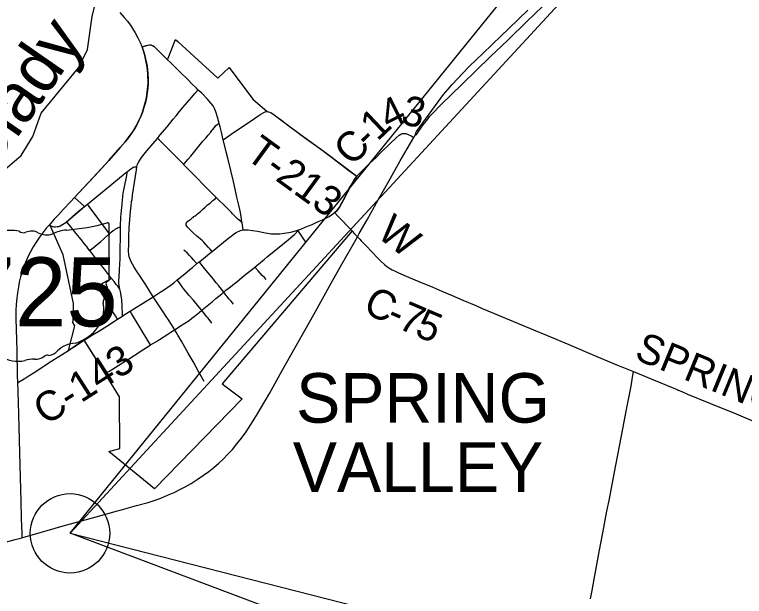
# Model space of a CAD drawing. Extents: x -19.5 to 44.1, y 0 to 22.
# Drawn here: x 5.174 to 6.569, y 16.047 to 17.159 of the extents above; entities that cross this region are included whole.
import ezdxf

# ---------------------------------------------------------------- set-up
doc = ezdxf.new("R2010")
doc.units = 0
for name, color, linetype in [('GM_X_City_Street', 7, 'Continuous'), ('GM_X_Corporation', 7, 'Continuous'), ('GM_X_Corporation_Text', 7, 'Continuous'), ('GM_X_County_Road', 7, 'Continuous'), ('GM_X_County_Road_Text', 7, 'Continuous'), ('GM_X_Minor_River', 7, 'Continuous'), ('GM_X_Minor_River_Text', 7, 'Continuous'), ('GM_X_State_Location', 7, 'Continuous'), ('GM_X_State_Route', 7, 'Continuous'), ('GM_X_State_Shield', 7, 'Continuous'), ('GM_X_Township_Road', 7, 'Continuous'), ('GM_X_Township_Road_Text', 7, 'Continuous'), ('GM_X_Township_Subdivision', 7, 'Continuous'), ('GM_X_US_Route', 7, 'Continuous'), ('SH_Text', 7, 'Continuous')]:
    doc.layers.add(name, color=color, linetype=linetype)

msp = doc.modelspace()

# ---------------------------------------------------------------- linework, layer by layer
at = {"layer": 'GM_X_City_Street'}
for points in [[(5.4716, 17.0678), (5.4663, 17.0729)], [(5.525, 17.015), (5.5213, 17.0185), (5.5123, 17.0274), (5.5054, 17.0344), (5.49, 17.0498), (5.4716, 17.0678)], [(5.4468, 16.9226), (5.4517, 16.9285), (5.4654, 16.9449), (5.477, 16.959), (5.4825, 16.9656), (5.4891, 16.9738), (5.4951, 16.981), (5.5038, 16.9912), (5.5124, 17.0012), (5.5185, 17.0081), (5.5238, 17.0138), (5.525, 17.015)], [(5.5651, 16.9511), (5.5619, 16.9628), (5.5585, 16.9734), (5.556, 16.9797), (5.5534, 16.9845), (5.5498, 16.9894), (5.5424, 16.9977), (5.5316, 17.0087), (5.525, 17.015)], [(5.5726, 16.92), (5.5742, 16.9211), (5.5877, 16.9304), (5.602, 16.9403), (5.6258, 16.9561), (5.6391, 16.9652), (5.6446, 16.9689), (5.6491, 16.9715), (5.6531, 16.9732), (5.6568, 16.974)], [(5.497, 16.8724), (5.4987, 16.8745), (5.5056, 16.8828), (5.5107, 16.8887), (5.5288, 16.9108), (5.534, 16.917), (5.5392, 16.9232), (5.5436, 16.9284), (5.5487, 16.9345), (5.5509, 16.9374), (5.552, 16.9388), (5.5557, 16.9433), (5.5581, 16.9463), (5.5617, 16.9496), (5.5651, 16.9511)], [(5.5726, 16.92), (5.5694, 16.9347), (5.5668, 16.9449), (5.5651, 16.9511)], [(5.4077, 16.8681), (5.4091, 16.8733), (5.4112, 16.8776), (5.4166, 16.886), (5.4268, 16.8985), (5.4468, 16.9226)], [(5.497, 16.8724), (5.4965, 16.873), (5.4923, 16.8776), (5.4887, 16.8814), (5.4827, 16.8874), (5.4639, 16.9063), (5.4572, 16.9128), (5.45, 16.9196), (5.4468, 16.9226)], [(5.6088, 16.7612), (5.6085, 16.7632), (5.607, 16.7724), (5.6055, 16.7808), (5.6043, 16.7867), (5.6025, 16.7949), (5.5999, 16.8053), (5.5988, 16.8101), (5.5973, 16.8167), (5.5923, 16.8398), (5.5872, 16.8612), (5.5813, 16.8845), (5.5781, 16.8966), (5.573, 16.9177), (5.5726, 16.92)], [(5.4386, 16.6199), (5.4245, 16.6423), (5.4194, 16.6502), (5.4124, 16.6609), (5.4081, 16.6677), (5.4026, 16.6766), (5.3995, 16.6823), (5.397, 16.6866), (5.3941, 16.6929), (5.3929, 16.6964), (5.3922, 16.7007), (5.3919, 16.7069), (5.3922, 16.7212), (5.3924, 16.7349), (5.3929, 16.7518), (5.3939, 16.7672), (5.3954, 16.7833), (5.3964, 16.7931), (5.3976, 16.8016), (5.3983, 16.8057), (5.3995, 16.8141), (5.4033, 16.838), (5.407, 16.8624), (5.4077, 16.8681)], [(5.3997, 16.8666), (5.4008, 16.8672), (5.4019, 16.8676), (5.4031, 16.868), (5.4039, 16.8681), (5.4053, 16.8682), (5.4077, 16.8681)], [(5.5595, 16.8093), (5.5594, 16.8094), (5.5485, 16.8203), (5.5377, 16.8313), (5.5338, 16.8353), (5.5241, 16.8449), (5.5089, 16.8602), (5.5079, 16.861), (5.4985, 16.8707), (5.497, 16.8724)], [(5.3131, 16.797), (5.345, 16.8231), (5.3744, 16.8469), (5.3887, 16.8588), (5.3896, 16.8594)], [(5.3761, 16.7537), (5.3761, 16.755), (5.377, 16.7718), (5.3774, 16.778), (5.378, 16.7848), (5.3787, 16.7904), (5.3795, 16.7977), (5.3802, 16.8039), (5.3809, 16.8113), (5.3816, 16.818), (5.3832, 16.827), (5.3881, 16.8513), (5.3883, 16.8526), (5.3896, 16.8594)], [(5.3896, 16.8594), (5.3961, 16.8643), (5.3997, 16.8666)], [(5.5513, 16.7064), (5.5502, 16.7077), (5.5479, 16.7106), (5.544, 16.7148), (5.5354, 16.7239), (5.5329, 16.7264), (5.5283, 16.7307), (5.5221, 16.7359), (5.5153, 16.7423), (5.508, 16.7491), (5.5048, 16.752), (5.5029, 16.7545), (5.5018, 16.7567), (5.5017, 16.7585), (5.5021, 16.7603), (5.5031, 16.7618), (5.5053, 16.764), (5.5106, 16.7683), (5.5135, 16.7705), (5.515, 16.7716), (5.5167, 16.7729), (5.519, 16.7745), (5.5207, 16.7757), (5.523, 16.7775), (5.5259, 16.7801), (5.529, 16.783), (5.5329, 16.7867), (5.5379, 16.7912), (5.5428, 16.7953), (5.5474, 16.799), (5.5529, 16.8037), (5.5579, 16.8079), (5.5595, 16.8093)], [(5.6088, 16.7612), (5.6061, 16.7636), (5.6009, 16.7681), (5.5957, 16.7731), (5.5922, 16.7766), (5.5905, 16.7784), (5.5887, 16.7806), (5.5857, 16.7837), (5.5828, 16.7868), (5.5787, 16.7905), (5.5595, 16.8093)], [(5.2734, 16.7633), (5.2746, 16.7642), (5.2773, 16.7667), (5.28, 16.7691), (5.2827, 16.7716), (5.2851, 16.7736), (5.2893, 16.7772), (5.2953, 16.7825), (5.3075, 16.7924), (5.3131, 16.797)], [(5.3554, 16.7403), (5.3535, 16.7428), (5.3164, 16.7926), (5.3131, 16.797)], [(5.715, 16.7473), (5.7208, 16.7493), (5.7294, 16.7529), (5.7355, 16.7554), (5.7424, 16.7582), (5.7489, 16.7609), (5.7564, 16.7642), (5.7625, 16.7671), (5.7688, 16.77), (5.7749, 16.7733), (5.7797, 16.7764), (5.7843, 16.7797), (5.7856, 16.7807)], [(5.2398, 16.7568), (5.2436, 16.7552), (5.2462, 16.7542), (5.2488, 16.7537), (5.2519, 16.7535), (5.2555, 16.7538), (5.2583, 16.7543), (5.2613, 16.7553), (5.2655, 16.7577), (5.2702, 16.7608), (5.2734, 16.7633)], [(5.3174, 16.7081), (5.3173, 16.7082), (5.3139, 16.7126), (5.3117, 16.7156), (5.3106, 16.7171), (5.3069, 16.7219), (5.3036, 16.7262), (5.2982, 16.7328), (5.2915, 16.741), (5.2813, 16.7535), (5.2755, 16.7607), (5.2734, 16.7633)], [(5.6107, 16.7477), (5.6088, 16.7612)], [(5.3554, 16.7403), (5.3586, 16.7431), (5.3624, 16.7462), (5.3648, 16.748), (5.3664, 16.749), (5.3701, 16.7512), (5.3719, 16.752), (5.3746, 16.7531), (5.3761, 16.7537)], [(5.3753, 16.6345), (5.3739, 16.6404), (5.3732, 16.6465), (5.3732, 16.6515), (5.3735, 16.6557), (5.3746, 16.6716), (5.3756, 16.6921), (5.3759, 16.7142), (5.3761, 16.7303), (5.3761, 16.7433), (5.3761, 16.7537)], [(5.5513, 16.7064), (5.5801, 16.7299), (5.5902, 16.7376), (5.5944, 16.7406), (5.5975, 16.7424), (5.6002, 16.7439), (5.6033, 16.7452), (5.606, 16.7463), (5.6107, 16.7477)], [(5.6107, 16.7477), (5.6157, 16.748), (5.6204, 16.7478), (5.6287, 16.7467), (5.6383, 16.745), (5.6535, 16.7421), (5.6645, 16.7401), (5.6691, 16.7399), (5.6729, 16.7398), (5.6769, 16.74), (5.6807, 16.7402), (5.6889, 16.7413), (5.6979, 16.7427), (5.7047, 16.7442), (5.7111, 16.746), (5.715, 16.7473)], [(5.6331, 16.6763), (5.6515, 16.6917), (5.6575, 16.6967), (5.6662, 16.7036), (5.6738, 16.7099), (5.6796, 16.7145), (5.6971, 16.7288), (5.7064, 16.7366), (5.709, 16.7389), (5.7116, 16.7414), (5.7127, 16.7427), (5.7133, 16.7437), (5.715, 16.7473)], [(5.7308, 16.7241), (5.7257, 16.732), (5.7229, 16.7359), (5.7206, 16.7392), (5.7174, 16.7438), (5.715, 16.7473)], [(5.3174, 16.7081), (5.3189, 16.7093), (5.324, 16.7136), (5.3388, 16.7256), (5.3442, 16.7305), (5.3535, 16.7388), (5.3554, 16.7403)], [(5.3592, 16.655), (5.3535, 16.6626), (5.3454, 16.6727), (5.3373, 16.6829), (5.3291, 16.6931), (5.3238, 16.7), (5.3174, 16.7081)], [(5.5225, 16.6831), (5.5212, 16.6846), (5.5157, 16.6905), (5.5118, 16.6946), (5.5082, 16.6988), (5.5035, 16.7036), (5.4975, 16.709)], [(5.5267, 16.6866), (5.5277, 16.6873), (5.5387, 16.6962), (5.5463, 16.7024), (5.5513, 16.7064)], [(5.4847, 16.652), (5.4869, 16.6538), (5.4996, 16.6639), (5.509, 16.6717), (5.5117, 16.674), (5.5139, 16.6759), (5.5212, 16.682), (5.5225, 16.6831)], [(5.5225, 16.6831), (5.5233, 16.6837), (5.5243, 16.6845), (5.5251, 16.6853), (5.5267, 16.6866)], [(5.5736, 16.6287), (5.5641, 16.6408), (5.5593, 16.6466), (5.5539, 16.6532), (5.5441, 16.6653), (5.5371, 16.674), (5.5278, 16.6852), (5.5267, 16.6866)], [(5.5736, 16.6287), (5.5742, 16.6292), (5.5779, 16.6321), (5.5867, 16.639), (5.5945, 16.6453), (5.5988, 16.6486), (5.6084, 16.6563), (5.6162, 16.6627), (5.6237, 16.669), (5.6293, 16.6732), (5.6331, 16.6763)], [(5.655, 16.6528), (5.6517, 16.6563), (5.6473, 16.6605), (5.6395, 16.6691), (5.6338, 16.6755), (5.6331, 16.6763)], [(5.3708, 16.577), (5.3695, 16.5789), (5.3665, 16.5835), (5.3581, 16.5965), (5.3542, 16.603), (5.3487, 16.6123), (5.3455, 16.6177), (5.3435, 16.6208), (5.3422, 16.6229), (5.3397, 16.627), (5.3376, 16.6309), (5.3365, 16.633), (5.3358, 16.6348), (5.3356, 16.636), (5.3354, 16.6378), (5.3357, 16.6393), (5.336, 16.6402), (5.3364, 16.6409), (5.3375, 16.6422), (5.3396, 16.644), (5.3422, 16.6457), (5.3443, 16.6469), (5.3503, 16.6501), (5.3522, 16.6511), (5.3574, 16.654), (5.3592, 16.655)], [(5.3753, 16.6345), (5.3709, 16.6399), (5.3682, 16.6433), (5.364, 16.6487), (5.3592, 16.655)], [(5.4386, 16.6199), (5.448, 16.626), (5.4521, 16.6286), (5.4554, 16.6307), (5.4601, 16.6338), (5.4647, 16.6367), (5.4666, 16.638), (5.4695, 16.6401), (5.4724, 16.6422), (5.4788, 16.6471), (5.4847, 16.652)], [(5.5316, 16.594), (5.5302, 16.5957), (5.5203, 16.6074), (5.5152, 16.6136), (5.5072, 16.6231), (5.4963, 16.6365), (5.4944, 16.639), (5.4889, 16.6464), (5.4847, 16.652)], [(5.3801, 16.5829), (5.38, 16.5865), (5.3792, 16.6018), (5.3788, 16.6141), (5.3778, 16.6221), (5.3765, 16.6295), (5.3753, 16.6345)], [(5.3948, 16.5923), (5.4018, 16.5968), (5.4386, 16.6199)], [(5.4798, 16.5566), (5.4781, 16.5595), (5.4726, 16.5684), (5.4691, 16.574), (5.4626, 16.5838), (5.4606, 16.5872), (5.4513, 16.6007), (5.4425, 16.614), (5.4386, 16.6199)], [(5.5316, 16.594), (5.5322, 16.5945), (5.5359, 16.5975), (5.5515, 16.6103), (5.5586, 16.6162), (5.5699, 16.6257), (5.5721, 16.6275), (5.5736, 16.6287)], [(5.5925, 16.6056), (5.5879, 16.6111), (5.5836, 16.6159), (5.5801, 16.6201), (5.5778, 16.6229), (5.5756, 16.6258), (5.5736, 16.6287)], [(5.3801, 16.5829), (5.3836, 16.5851), (5.3935, 16.5914), (5.3948, 16.5923)], [(5.4338, 16.5276), (5.4306, 16.5331), (5.3975, 16.5877), (5.3948, 16.5923)], [(5.4798, 16.5566), (5.4806, 16.5571), (5.4912, 16.5641), (5.4996, 16.5694), (5.5073, 16.5746), (5.5128, 16.5787), (5.5172, 16.5822), (5.5265, 16.5898), (5.5316, 16.594)], [(5.5511, 16.5696), (5.5438, 16.5787), (5.5415, 16.5814), (5.5363, 16.588), (5.5316, 16.594)], [(5.307, 16.5367), (5.3227, 16.5467), (5.3348, 16.5542), (5.3499, 16.5636), (5.3708, 16.577)], [(5.3708, 16.577), (5.3801, 16.5829)], [(5.4338, 16.5276), (5.438, 16.5302), (5.4449, 16.5345), (5.4509, 16.5383), (5.4666, 16.5483), (5.4727, 16.5522), (5.4798, 16.5566)], [(5.5362, 16.458), (5.5311, 16.4669), (5.5261, 16.4755), (5.5208, 16.4851), (5.5149, 16.4958), (5.5058, 16.5121), (5.493, 16.5347), (5.4859, 16.5464), (5.4824, 16.5521), (5.4798, 16.5566)], [(5.3821, 16.4948), (5.3917, 16.5005), (5.4023, 16.5073), (5.4211, 16.5195), (5.4312, 16.5259), (5.4338, 16.5276)], [(5.3473, 16.4763), (5.3489, 16.4761), (5.3505, 16.4759), (5.3516, 16.4761), (5.3539, 16.4769), (5.3589, 16.4798), (5.3661, 16.4846), (5.3731, 16.4893), (5.3799, 16.4934), (5.3821, 16.4948)]]:
    msp.add_lwpolyline(points, dxfattribs=at)
at = {"layer": 'GM_X_Corporation'}
msp.add_lwpolyline([(5.2669, 16.6997), (5.2417, 16.756), (5.2462, 16.7542), (5.2519, 16.7535), (5.2583, 16.7543), (5.2655, 16.7577), (5.2718, 16.762), (5.3075, 16.7924), (5.2885, 16.8096), (5.3316, 16.8559), (5.3539, 16.8802), (5.3758, 16.9048), (5.3851, 16.9157), (5.3991, 16.9346), (5.4097, 16.9525), (5.4152, 16.9644), (5.4183, 16.9726), (5.4212, 16.9815), (5.4237, 16.9906), (5.4259, 17.0003), (5.4292, 17.0275), (5.4288, 17.0457), (5.4273, 17.0596), (5.4244, 17.0747), (5.4222, 17.0837), (5.4176, 17.0974), (5.4286, 17.1007), (5.4326, 17.1012), (5.435, 17.1009), (5.4374, 17.1003), (5.4408, 17.0981), (5.4663, 17.0729), (5.4814, 17.1113), (5.4864, 17.1071), (5.5624, 17.0375), (5.5838, 17.0579), (5.6293, 16.9976), (5.6568, 16.974), (5.6593, 16.9735), (5.6634, 16.9718), (5.6699, 16.9677), (5.7056, 16.941), (5.7706, 16.8935), (5.8284, 16.8505), (5.8224, 16.8422), (5.817, 16.8333), (5.8024, 16.805), (5.7948, 16.7911), (5.7913, 16.786), (5.7892, 16.7836), (5.7856, 16.7807), (5.7931, 16.7727), (5.819, 16.7455), (5.5706, 16.4534), (5.6087, 16.4244), (5.4413, 16.2527), (5.3539, 16.3239), (5.3752, 16.3298), (5.3742, 16.4283), (5.3438, 16.4785), (5.307, 16.5367), (5.2766, 16.5171), (5.2891, 16.5642), (5.2844, 16.5716), (5.2858, 16.5727), (5.2862, 16.6067)], close=True, dxfattribs=at)
at = {"layer": 'GM_X_County_Road'}
for points in [[(5.4176, 17.0974), (5.4256, 17.0999), (5.4288, 17.1008), (5.4309, 17.1011), (5.4326, 17.1012), (5.4342, 17.1011), (5.4358, 17.1008), (5.4374, 17.1003), (5.4391, 17.0994), (5.4408, 17.0981), (5.4549, 17.084), (5.4663, 17.0729)], [(5.8284, 16.8505), (5.8377, 16.8601), (5.8527, 16.8749), (5.8642, 16.8854), (5.8735, 16.8946), (5.8917, 16.9125), (5.9034, 16.9237), (5.909, 16.9285), (5.912, 16.9305), (5.9136, 16.9312), (5.9152, 16.9317), (5.9167, 16.932), (5.9181, 16.9321), (5.92, 16.9319), (5.9218, 16.9316), (5.9261, 16.9299), (5.9318, 16.9271), (5.9373, 16.9243)], [(5.7856, 16.7807), (5.7892, 16.7836), (5.7913, 16.786), (5.7948, 16.7911), (5.7999, 16.8003), (5.8039, 16.8079), (5.8076, 16.8151), (5.8114, 16.8227), (5.8136, 16.8271), (5.8146, 16.8292), (5.8155, 16.8307), (5.817, 16.8333), (5.8224, 16.8422), (5.8284, 16.8505)], [(5.7856, 16.7807), (5.7931, 16.7727), (5.7999, 16.7656), (5.8098, 16.7553), (5.819, 16.7455)], [(5.819, 16.7455), (5.8191, 16.7453), (5.8239, 16.7402), (5.8292, 16.7345)], [(5.8292, 16.7345), (5.8338, 16.7297), (5.8363, 16.727), (5.8445, 16.7185), (5.8578, 16.7046), (5.8663, 16.6957), (5.8741, 16.6876), (5.8809, 16.6813), (5.8853, 16.6778), (5.8895, 16.6749), (5.8954, 16.6714), (5.9016, 16.6684), (5.9079, 16.6656), (5.9267, 16.6574), (5.9467, 16.6489), (5.9731, 16.638), (5.9907, 16.6303), (6.0101, 16.6221), (6.0306, 16.6132), (6.0555, 16.6028), (6.0678, 16.5974), (6.0893, 16.5886), (6.1506, 16.563), (6.1661, 16.5565), (6.1908, 16.5462), (6.2332, 16.5285), (6.287, 16.5059), (6.3265, 16.4893), (6.3328, 16.4866), (6.3345, 16.4859), (6.3409, 16.4834), (6.3573, 16.4767)], [(5.2867, 16.5236), (5.2971, 16.5305), (5.307, 16.5367)], [(5.2766, 16.5171), (5.286, 16.5232), (5.2867, 16.5236)], [(5.1795, 16.4554), (5.1845, 16.4586), (5.192, 16.4632), (5.1979, 16.4668), (5.2163, 16.4784), (5.2402, 16.4939), (5.2686, 16.5119), (5.2766, 16.5171)], [(6.3573, 16.4767), (6.3955, 16.461), (6.434, 16.4452), (6.4402, 16.4424), (6.4425, 16.4414), (6.4494, 16.4385), (6.4602, 16.4339), (6.5039, 16.4159), (6.5534, 16.3958), (6.5878, 16.3814)]]:
    msp.add_lwpolyline(points, dxfattribs=at)
at = {"layer": 'GM_X_Minor_River'}
msp.add_lwpolyline([(5.1457, 16.8556), (5.1866, 16.8897), (5.209, 16.9264), (5.2246, 16.9706), (5.2961, 17.0572), (5.3135, 17.0925), (5.322, 17.1558), (5.331, 17.1925)], dxfattribs=at)
at = {"layer": 'GM_X_State_Route'}
for points in [[(5.3752, 17.1629), (5.3836, 17.1537), (5.3896, 17.1465), (5.3927, 17.1424), (5.3953, 17.1391), (5.3994, 17.1328), (5.4045, 17.1242), (5.4096, 17.1149), (5.4139, 17.1059), (5.4154, 17.1023), (5.4176, 17.0974), (5.4199, 17.0909), (5.4222, 17.0837), (5.4244, 17.0747), (5.4266, 17.0643), (5.428, 17.055), (5.4288, 17.0457), (5.4292, 17.0363), (5.4292, 17.0275), (5.4286, 17.0188), (5.4275, 17.0095), (5.4259, 17.0003), (5.4239, 16.9911), (5.4212, 16.9815), (5.4183, 16.9726), (5.4152, 16.9644), (5.4116, 16.9564), (5.4077, 16.9486), (5.4033, 16.941), (5.3982, 16.9332), (5.392, 16.9246), (5.3851, 16.9157), (5.3758, 16.9048), (5.3539, 16.8802), (5.3346, 16.8591), (5.3172, 16.8404), (5.2885, 16.8096), (5.2804, 16.8013), (5.2674, 16.7872), (5.2575, 16.7767), (5.2498, 16.7682), (5.2398, 16.7568), (5.235, 16.7514), (5.2288, 16.7437), (5.2215, 16.7337), (5.2148, 16.724), (5.2093, 16.7151), (5.2041, 16.7059), (5.2, 16.6976), (5.1959, 16.6886), (5.1922, 16.6794), (5.1888, 16.6695), (5.1852, 16.6576), (5.1828, 16.648), (5.181, 16.6389), (5.1791, 16.6273), (5.1779, 16.6169), (5.177, 16.6051), (5.1765, 16.5934), (5.1765, 16.5785), (5.1779, 16.5164), (5.179, 16.4698), (5.1795, 16.4554)], [(5.1795, 16.4554), (5.1801, 16.4388), (5.1811, 16.3953), (5.184, 16.2972), (5.1855, 16.2289), (5.1866, 16.196), (5.1875, 16.1671), (5.1878, 16.1592)]]:
    msp.add_lwpolyline(points, dxfattribs=at)
at = {"layer": 'GM_X_State_Shield'}
for p, q in [((5.3549, 16.6529), (5.3549, 16.7576)), ((5.3548, 16.6529), (5.3549, 16.6529))]:
    msp.add_line(p, q, dxfattribs=at)
for centre, major_axis, start_param, end_param in [((5.2375, 17.0255), (0.3495, 0), 4.814394, 5.042369), ((5.3512, 16.758), (0.00367, 0), 6.141152, 7.989035), ((5.1603, 16.6403), (0.133, 0), 1.404758, 1.657858), ((5.1905, 16.7507), (0.0107, 0), 3.836095, 5.185415), ((5.2062, 16.7275), (0.0222, 0), 0.950623, 2.079405), ((5.282, 16.6915), (0.0703, 0), 1.699011, 2.107814), ((5.2349, 16.7593), (0.0267, 0), 4.081561, 5.145723), ((5.354, 16.6452), (0.00568, 0), 1.883978, 3.671073), ((5.351, 16.6525), (0.00393, 0), 5.05454, 6.418171), ((5.3179, 16.632), (0.0341, 0), 5.934695, 6.695948), ((5.368, 16.6091), (0.0248, 0), 2.387724, 3.262537), ((5.257, 16.5958), (0.0874, 0), 5.101752, 6.440018), ((5.2939, 16.4929), (0.0479, 0), 1.647645, 2.488434), ((5.1797, 16.5365), (0.0501, 0), 4.026481, 4.996735), ((5.2123, 16.5216), (0.0267, 0), 4.691044, 5.507374), ((5.2365, 16.5022), (0.00752, 0), 1.147584, 2.315152), ((5.2332, 16.5297), (0.0282, 0), 4.937069, 5.64225), ((5.2086, 16.4674), (0.0412, 0), 1.495662, 1.94098)]:
    msp.add_ellipse(centre, major_axis=major_axis, ratio=0.8, start_param=start_param, end_param=end_param, dxfattribs=at)
at = {"layer": 'GM_X_Township_Road'}
for points in [[(5.6568, 16.974), (5.6593, 16.9735), (5.6634, 16.9718), (5.6699, 16.9677), (5.6774, 16.962), (5.6838, 16.9572), (5.69, 16.9526), (5.6994, 16.9455), (5.7088, 16.9386), (5.7182, 16.9315), (5.7351, 16.919), (5.7584, 16.9023), (5.7693, 16.8944), (5.7821, 16.885), (5.813, 16.8614), (5.8284, 16.8505)], [(6.2749, 16.0425), (6.2779, 16.0583), (6.2818, 16.0797), (6.2877, 16.1115), (6.2915, 16.1323), (6.2983, 16.1683), (6.3063, 16.2097), (6.3103, 16.2305), (6.3234, 16.2976), (6.3342, 16.3537), (6.3437, 16.4044), (6.3523, 16.4489), (6.3554, 16.4661), (6.3573, 16.4767)]]:
    msp.add_lwpolyline(points, dxfattribs=at)
at = {"layer": 'GM_X_Township_Subdivision'}
msp.add_lwpolyline([(5.3473, 16.4763), (5.346, 16.4766), (5.3451, 16.4772), (5.3444, 16.4778), (5.3438, 16.4785), (5.3411, 16.4826), (5.3353, 16.4921), (5.3233, 16.5109), (5.3151, 16.524), (5.307, 16.5367)], dxfattribs=at)
at = {"layer": 'GM_X_US_Route'}
for points in [[(5.9399, 16.9286), (5.9407, 16.9291), (5.9413, 16.9295), (5.942, 16.9302), (5.9426, 16.9309), (5.9431, 16.9316), (5.9439, 16.9327), (5.9457, 16.9354), (5.9551, 16.9485), (5.9613, 16.9563), (5.9679, 16.9648), (5.9765, 16.9742), (5.9829, 16.9808), (5.9893, 16.9873), (6.0294, 17.0263), (6.083, 17.0781), (6.1165, 17.1105), (6.154, 17.1468), (6.183, 17.1749), (6.2067, 17.1978), (6.2097, 17.2008), (6.2201, 17.2108), (6.2795, 17.2682), (6.2851, 17.2737)], [(5.9399, 16.9286), (5.9401, 16.9302), (5.9404, 16.9315), (5.9408, 16.9324), (5.9411, 16.9334), (5.9418, 16.9345), (5.9424, 16.9354), (5.9938, 17.0061), (6.0025, 17.0167), (6.0103, 17.0256), (6.0205, 17.0366), (6.0416, 17.0587), (6.0584, 17.0745), (6.0677, 17.0836), (6.0876, 17.1024), (6.1189, 17.1326), (6.155, 17.1677)], [(5.8292, 16.7345), (5.8328, 16.741), (5.8476, 16.7669), (5.8688, 16.8049), (5.889, 16.8406), (5.911, 16.8796), (5.9244, 16.9027), (5.9373, 16.9243), (5.9399, 16.9286)], [(5.1878, 16.1592), (5.1939, 16.1609), (5.2227, 16.1691), (5.2359, 16.1728), (5.267, 16.1817), (5.3299, 16.199), (5.3706, 16.2104), (5.3755, 16.2117), (5.4071, 16.2205), (5.4291, 16.2268), (5.4409, 16.2306), (5.4532, 16.235), (5.4664, 16.2403), (5.4789, 16.2458), (5.49, 16.2512), (5.4999, 16.2565), (5.5111, 16.263), (5.5226, 16.2703), (5.5349, 16.2787), (5.5449, 16.286), (5.5546, 16.2937), (5.564, 16.3018), (5.5731, 16.3102), (5.5818, 16.319), (5.5902, 16.3281), (5.599, 16.3385), (5.6078, 16.3498), (5.6165, 16.3618), (5.6257, 16.3758), (5.6363, 16.3926), (5.6609, 16.435), (5.6855, 16.4789), (5.7458, 16.5861), (5.7793, 16.6456), (5.7997, 16.6819), (5.8186, 16.7155), (5.8292, 16.7345)], [(4.8536, 16.0455), (4.8592, 16.0491), (4.8697, 16.0557), (4.8781, 16.0608), (4.8873, 16.066), (4.8941, 16.0694), (4.8986, 16.0715), (4.9072, 16.0757), (4.9111, 16.0776), (4.9244, 16.0831), (4.9371, 16.088), (4.9475, 16.0917), (4.9625, 16.0965), (4.978, 16.101), (5.0007, 16.1072), (5.0737, 16.1276), (5.1139, 16.1386), (5.1565, 16.1505), (5.1752, 16.1557), (5.1851, 16.1584), (5.1878, 16.1592)]]:
    msp.add_lwpolyline(points, dxfattribs=at)
at = {"layer": 'SH_Text'}
for points in [[(6.5995, 17.5973), (5.2798, 16.1676), (6.5995, 17.7973)], [(6.926, 15.5471), (5.2798, 16.1676), (6.926, 15.7471)]]:
    msp.add_lwpolyline(points, close=True, dxfattribs=at)
msp.add_circle((5.2798, 16.1676), 0.0759, dxfattribs=at)

# ---------------------------------------------------------------- texts
at = {"layer": 'GM_X_Corporation_Text'}
for s, p in [('SPRING', (5.712, 16.3791)), ('VALLEY', (5.7057, 16.2468))]:
    msp.add_text(s, height=0.0947, rotation=0, dxfattribs=at).set_placement(p)
at = {"layer": 'GM_X_County_Road_Text'}
for s, height, rotation, p in [('4', 0.0568, 26.3017, (5.889, 16.937)), ('3', 0.0568, 346.0609, (5.9099, 16.9513)), ('1', 0.0568, 43.5268, (5.8675, 16.9157)), ('C', 0.0568, 44.5462, (5.8181, 16.8673)), ('-', 0.0568, 44.0227, (5.851, 16.8997)), ('W', 0.0568, 322.2531, (5.864, 16.7361)), ('C', 0.0568, 333.3704, (5.8372, 16.592)), ('7', 0.0568, 336.921, (5.9039, 16.5604)), ('-', 0.0568, 337.0163, (5.8825, 16.5695)), ('5', 0.0568, 336.9391, (5.9362, 16.5466)), ('SPRING', 0.05682, 337.6606, (6.3564, 16.5016)), ('C-143', 0.05682, 32.7061, (5.2334, 16.3727))]:
    msp.add_text(s, height=height, rotation=rotation, dxfattribs=at).set_placement(p)
at = {"layer": 'GM_X_Minor_River_Text'}
msp.add_text('Glady', height=0.09468, rotation=55.1514, dxfattribs=at).set_placement((5.1206, 16.8392))
at = {"layer": 'GM_X_State_Location'}
for s in ['s', 'r']:
    msp.add_text(s, height=0.000189, dxfattribs=at).set_placement((5.1864, 16.6358))
at = {"layer": 'GM_X_State_Shield'}
msp.add_text('725', height=0.13184, dxfattribs=at).set_placement((5.0768, 16.5632))
at = {"layer": 'GM_X_Township_Road_Text'}
msp.add_text('T-213', height=0.05682, rotation=323.9535, dxfattribs=at).set_placement((5.6125, 16.886))

doc.saveas('drawing.dxf')
